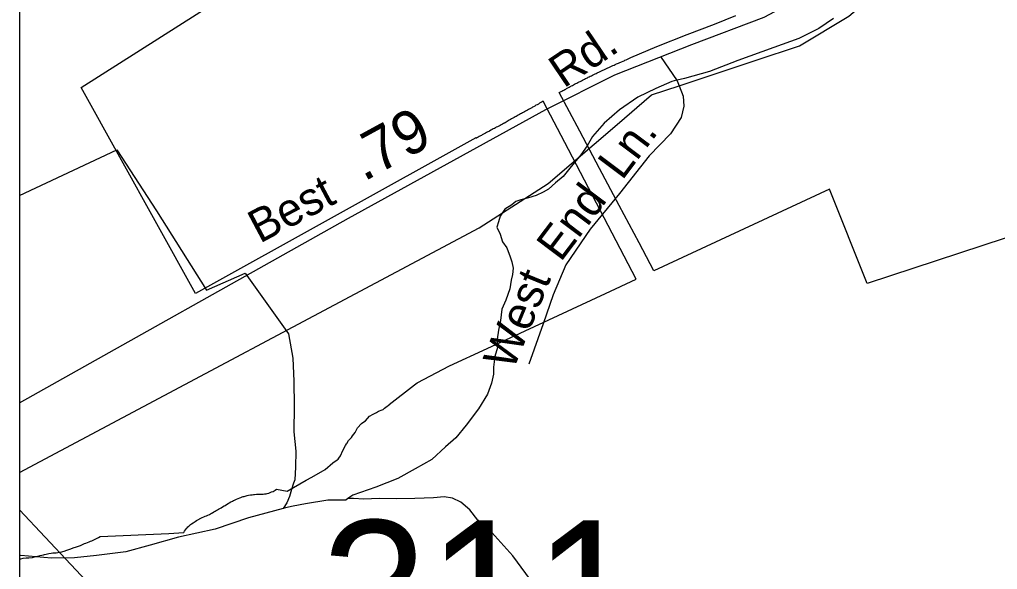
# Model space of a CAD drawing. Extents: x 2315291 to 2336543, y 597177 to 615230.
# Drawn here: x 2315744 to 2318553, y 599617 to 601198 of the extents above; entities that cross this region are included whole.
import ezdxf

# ---------------------------------------------------------------- set-up
doc = ezdxf.new("R2010")
doc.units = 0
for name, color, linetype in [('Exist Boundary Political City Limit New', 7, 'Continuous'), ('Exist Boundary Political Urban Extension UEB', 7, 'Continuous'), ('Exist Hydrographic Misc Water Feature', 7, 'Continuous'), ('Exist Road Non-System Type 51', 7, 'Continuous'), ('Exist Road Non-System Type 51 Label', 7, 'Continuous'), ('Exist Road Secondary Mileage Hundredths English Label', 7, 'Continuous'), ('Exist Road Secondary Structure Standard Bridge Number Label', 7, 'Continuous'), ('Exist Road Secondary Type 51 Attributed', 7, 'Continuous'), ('Exist Road Secondary Type 51 Label', 7, 'Continuous'), ('Exist Utilities Electrical Transmission Line', 7, 'Continuous'), ('Map Preparation Boundary City Limit Buffer Line', 7, 'Continuous')]:
    doc.layers.add(name, color=color, linetype=linetype)

msp = doc.modelspace()

# ---------------------------------------------------------------- linework, layer by layer
at = {"layer": 'Exist Boundary Political City Limit New'}
msp.add_line((2315744.5, 601767.6), (2315744.5, 599647.3), dxfattribs=at)
for points in [[(2315744.5, 604723.7), (2315744.5, 597529.5), (2327185.3, 597529.5)], [(2317108.8, 600884.8), (2317105.2, 600883), (2317101.8, 600881.1), (2317098.2, 600879.2), (2317094.5, 600877.2), (2317092, 600875.9), (2317089.2, 600874.4), (2317085.8, 600872.5), (2317083.2, 600871.1), (2317080.5, 600869.7), (2317077, 600867.8), (2317073.5, 600865.8), (2317071, 600864.4), (2317068.2, 600862.9), (2317064.8, 600861), (2317061.5, 600859.1), (2317057.8, 600857.1), (2317054.8, 600855.4), (2317055.2, 600857.5), (2316249.5, 600409.7), (2315921.8, 601002.4), (2316312.2, 601250.2)], [(2317415.8, 601050.1), (2317419.5, 601051.8), (2317423, 601053.5), (2317426.8, 601055.2), (2317430.2, 601056.8), (2317434, 601058.6), (2317437.5, 601060.2), (2317441.2, 601061.9), (2317444.8, 601063.5), (2317448.5, 601065.2), (2317452.2, 601066.8), (2317455.8, 601068.4), (2317459.5, 601070.1), (2317462.2, 601071.3), (2317465, 601072.6), (2317468.8, 601074.1), (2317471.5, 601075.3), (2317474, 601076.5), (2317478, 601078.1), (2317480.8, 601079.3), (2317483.2, 601080.5), (2317487.2, 601082.1), (2317500, 601088.4), (2317574.8, 601120.2), (2317662.2, 601154.6), (2317740.8, 601184.1), (2317801.8, 601209.1)], [(2319038.8, 600721.7), (2318179, 600438.4), (2318071, 600710), (2317566.8, 600475.2), (2317524, 600555.8), (2317467, 600663.4), (2317410.5, 600769.6), (2317353.8, 600876.4), (2317294.5, 600987.6), (2317298, 600989.5), (2317302, 600991.7), (2317305.5, 600993.6), (2317308.2, 600995), (2317310.8, 600996.5), (2317313.5, 600997.9), (2317316, 600999.3), (2317319.5, 601001.2), (2317323, 601003.2), (2317326.5, 601005), (2317330, 601006.9), (2317332.8, 601008.3), (2317335.2, 601009.7), (2317339, 601011.6), (2317342.5, 601013.5), (2317345.2, 601014.9), (2317347.8, 601016.2), (2317351.5, 601018.1), (2317354.8, 601019.9), (2317358.5, 601021.8), (2317361.2, 601023.1), (2317363.8, 601024.5), (2317367.2, 601026.3), (2317370, 601027.7), (2317372.8, 601029), (2317375.5, 601030.4), (2317378, 601031.7), (2317380.8, 601033.1), (2317383.5, 601034.4), (2317387, 601036.1), (2317390.5, 601037.9), (2317394.2, 601039.7), (2317397.8, 601041.4), (2317400.5, 601042.8), (2317403.2, 601044.1), (2317406, 601045.3), (2317408.5, 601046.6), (2317412.2, 601048.3), (2317415.8, 601050.1)], [(2316430, 599833.1), (2316435, 599832.9), (2316438.2, 599832.9), (2316443.8, 599833.1), (2316448.2, 599833.7), (2316452.5, 599834.4), (2316456.2, 599835.2), (2316460.2, 599836.4), (2316464.8, 599837.9), (2316468.5, 599839.3), (2316472.5, 599841.2), (2316478.8, 599844.9), (2316482.8, 599847.5), (2316512.8, 599841.5), (2316568, 599872.9), (2316584.5, 599882.1), (2316622.8, 599904.1), (2316644, 599922.9), (2316656.8, 599931.5), (2316659.8, 599933.6), (2316661.8, 599936.3), (2316666.8, 599942.9), (2316673.2, 599958.5), (2316680.8, 599972.6), (2316683.2, 599978), (2316684.8, 599978.7), (2316689, 599987.1), (2316695.8, 599994), (2316698, 599996.2), (2316701.2, 600000.5), (2316708.5, 600010.5), (2316711, 600015.8), (2316715, 600023.5), (2316726.8, 600036.5), (2316733.8, 600041.2), (2316738.2, 600044.3), (2316750, 600057.4), (2316760.5, 600062.6), (2316769.5, 600067.8), (2316776, 600071.7), (2316786.5, 600075.6), (2316789, 600076.9), (2316792.8, 600080.5), (2316800, 600085.6), (2316805.8, 600090.1), (2316806, 600090.9), (2316879, 600147.5), (2316886.5, 600153.3), (2316979.8, 600201.8), (2317087.5, 600251.9), (2317427.8, 600410.4), (2317515.8, 600451.4), (2317321.5, 600823.6), (2317248.8, 600962.6), (2317245.2, 600960.7), (2317241.8, 600958.8), (2317238.2, 600956.8), (2317234.8, 600954.8), (2317231.2, 600952.9), (2317227.8, 600951), (2317224.2, 600949), (2317220.8, 600947.1), (2317218.2, 600945.6), (2317215.8, 600944.2), (2317212.2, 600942.2), (2317208.8, 600940.2), (2317206.2, 600938.8), (2317203.5, 600937.3), (2317200, 600935.4), (2317197.5, 600933.9), (2317194.8, 600932.5), (2317191.2, 600930.6), (2317188.8, 600929.1), (2317186, 600927.6), (2317183.5, 600926.1), (2317180.8, 600924.7), (2317177.2, 600922.7), (2317173.8, 600920.8), (2317171.2, 600919.2), (2317168.5, 600917.8), (2317165, 600915.8), (2317161.5, 600913.8), (2317158, 600911.9), (2317154.5, 600909.9), (2317151, 600907.9), (2317147.8, 600906), (2317145.2, 600904.5), (2317142.5, 600903), (2317139, 600901), (2317136.5, 600899.6), (2317135.5, 600899), (2317134.5, 600898.5), (2317131.8, 600897.1), (2317128, 600895.2), (2317124.8, 600893.3), (2317121, 600891.4), (2317117.5, 600889.6), (2317114, 600887.8), (2317111.5, 600886.3), (2317108.8, 600884.8)], [(2315744.5, 599647.3), (2315747.8, 599647.4), (2315755.2, 599648.8), (2315763.5, 599650), (2315771, 599650.3), (2315782, 599651.2), (2315787.8, 599652.6), (2315797, 599655), (2315803.5, 599656.7), (2315812.8, 599658.9), (2315815.8, 599659.6), (2315821, 599660.8), (2315829, 599662.6), (2315835.2, 599663.4), (2315840, 599664), (2315845.2, 599664.5), (2315849.2, 599664.6), (2315854.8, 599665.4), (2315866, 599667.3), (2315868.8, 599667.9), (2315872.2, 599669.2), (2315879.8, 599672.1), (2315891.5, 599676.1), (2315898.8, 599678.8), (2315908.2, 599681.7), (2315914.2, 599683.5), (2315919.8, 599685.8), (2315925, 599688), (2315931.2, 599690.8), (2315935.2, 599692.4), (2315939.8, 599694.2), (2315944, 599696.2), (2315947.8, 599697.6), (2315952.2, 599699.2), (2315962, 599703.5), (2315971.2, 599708.5), (2315976.2, 599711.1), (2316173, 599720.1), (2316216.2, 599722.8), (2316218.5, 599726.8), (2316220.8, 599730.3), (2316223, 599733.2), (2316225.5, 599736.1), (2316228.2, 599739.3), (2316230.5, 599741.3), (2316233.5, 599744), (2316235.8, 599745.9), (2316238.8, 599748.1), (2316242.8, 599750.8), (2316245.8, 599752.7), (2316249, 599754.8), (2316253, 599757.2), (2316256.2, 599759.1), (2316260.2, 599761.5), (2316261.8, 599762.2), (2316264.8, 599763.8), (2316269, 599765.8), (2316274.2, 599768.1), (2316277.8, 599769.6), (2316281, 599770.9), (2316285.5, 599772.4), (2316289.8, 599774.7), (2316292.5, 599776.2), (2316295.5, 599778), (2316298.8, 599779.8), (2316303, 599782.2), (2316306, 599783.9), (2316309.2, 599785.7), (2316313.2, 599788.1), (2316316.2, 599789.9), (2316319.5, 599791.6), (2316323.8, 599794.1), (2316327.8, 599796.4), (2316332.5, 599799.1), (2316335.5, 599800.9), (2316339.2, 599803.1), (2316343.5, 599805.8), (2316346.5, 599807.8), (2316351.5, 599810.6), (2316355.8, 599813), (2316358.8, 599814.6), (2316361.5, 599816), (2316367.5, 599818.8), (2316372, 599820.7), (2316377.2, 599822.7), (2316380.5, 599823.9), (2316384, 599825.1), (2316387, 599825.9), (2316389.8, 599826.8), (2316392.8, 599827.6), (2316395.5, 599828.3), (2316398.5, 599829), (2316402, 599829.8), (2316408, 599830.9), (2316412.5, 599831.6), (2316416.2, 599832), (2316419.8, 599832.4), (2316425.5, 599832.8), (2316430, 599833.1)]]:
    msp.add_lwpolyline(points, dxfattribs=at)
at = {"layer": 'Exist Boundary Political Urban Extension UEB'}
for points in [[(2317638.9, 601007.3), (2317857.2, 601080), (2317984.6, 601122.5), (2318126.2, 601207.5), (2318310.3, 601363.2), (2318542.1, 601594.9)], [(2315744.5, 599894.9), (2317064.3, 600598.7), (2317262.5, 600726.1), (2317460.7, 600896), (2317559.8, 600980.9), (2317638.9, 601007.3)]]:
    msp.add_lwpolyline(points, dxfattribs=at)
at = {"layer": 'Exist Hydrographic Misc Water Feature'}
for points in [[(2318082.4, 601200.5), (2318040.6, 601171.9), (2317982.8, 601143.3), (2317911.2, 601116.8), (2317807.7, 601079.6), (2317726, 601048.5), (2317654.7, 601028.1), (2317624.8, 601021.6), (2317618.4, 601019.7), (2317572.5, 600999), (2317520.8, 600974.4), (2317467.5, 600937.8), (2317424.2, 600899.3), (2317390.2, 600861), (2317374.8, 600835), (2317356.7, 600808.9), (2317325.4, 600770.6), (2317305.7, 600746.4), (2317284, 600728.2), (2317264.3, 600710.1), (2317248.1, 600701.6), (2317228, 600691.6), (2317206.2, 600685.2), (2317184.3, 600679.1), (2317170.4, 600674.7), (2317158.7, 600664.8), (2317138.8, 600652.7), (2317125.2, 600632.5), (2317120.7, 600616.5), (2317115.2, 600600.3), (2317125.5, 600580.5), (2317132, 600558.4), (2317143.9, 600540.9), (2317154, 600515), (2317158.1, 600501), (2317162.8, 600482.9), (2317160.5, 600464.9), (2317157, 600448.8), (2317153.1, 600423.1), (2317141.4, 600390.8), (2317129.8, 600364.5), (2317126.3, 600332.6), (2317120.7, 600304.6), (2317116.8, 600278.5), (2317117, 600254.5), (2317109.3, 600228.5), (2317105.6, 600198.6), (2317105.8, 600178.4), (2317100, 600152.4), (2317088.3, 600120.6), (2317063.1, 600078.1), (2317027.2, 600031.6), (2316997.9, 599995.5), (2316968, 599969.2), (2316928.4, 599932.5), (2316880.6, 599906.1), (2316831.2, 599877.8), (2316767.6, 599852.9), (2316701.8, 599830.4), (2316687.9, 599820.3)], [(2315744.5, 600691.3), (2316023.7, 600822.6), (2316137.5, 600647.7), (2316281.9, 600419.6), (2316392.8, 600468.6), (2316464.4, 600367.4), (2316517.3, 600294.1), (2316529.8, 600224.5), (2316532.4, 600158.4), (2316533.3, 600086.5), (2316532, 600012.5), (2316538.4, 599956.4), (2316537, 599910.3), (2316535.3, 599874.5), (2316531.6, 599864.5), (2316525.5, 599846.3), (2316520.1, 599826.5), (2316511.9, 599808.3), (2316502.1, 599792.3)], [(2316687.9, 599820.3), (2316681.9, 599815.9), (2316630, 599815.6), (2316566.3, 599805), (2316530.4, 599798.6), (2316508.4, 599794.2), (2316502.1, 599792.3)], [(2317222.4, 599572), (2317161.5, 599655.3), (2317100.8, 599722.5), (2317060.4, 599758.2), (2317037.7, 599787.9), (2317011.6, 599809.7), (2316987.7, 599821.4), (2316963.7, 599825), (2316933.9, 599823), (2316880, 599820.2), (2316825.9, 599819.8), (2316777.7, 599821), (2316733.8, 599818.7), (2316703.5, 599820.4), (2316687.9, 599820.3)], [(2316502.1, 599792.3), (2316402.4, 599765.1), (2316306.7, 599732.1), (2316201.3, 599709), (2316119.3, 599686.1), (2316050, 599667.3), (2315965.7, 599656.5), (2315902.5, 599649.8), (2315836.1, 599649.2), (2315748.1, 599656.4), (2315744.5, 599655.9)]]:
    msp.add_lwpolyline(points, dxfattribs=at)
at = {"layer": 'Exist Road Non-System Type 51'}
for points in [[(2317585.9, 601091.7), (2317633.5, 601021.2), (2317638.9, 601007.3)], [(2317638.9, 601007.3), (2317650.6, 600977.4), (2317652.6, 600948.8), (2317644.9, 600916.4), (2317614.5, 600868.7), (2317553.5, 600805.8), (2317467.8, 600697.2), (2317384, 600595.2), (2317313.5, 600492.3), (2317277.3, 600406.6), (2317248.8, 600322.7), (2317206.9, 600206.4)]]:
    msp.add_lwpolyline(points, dxfattribs=at)
at = {"layer": 'Exist Road Secondary Type 51 Attributed'}
msp.add_lwpolyline([(2315744.5, 600095.6), (2316689.5, 600626.2), (2317256.4, 600939.2), (2317454.5, 601038.4), (2317675.4, 601126), (2317883, 601204.2), (2317991.6, 601263.2), (2318258.2, 601461.5), (2318357.3, 601541.5), (2318498.2, 601663.5)], dxfattribs=at)
at = {"layer": 'Exist Utilities Electrical Transmission Line'}
msp.add_line((2315744.5, 599788.2), (2316288, 599208.6), dxfattribs=at)
at = {"layer": 'Map Preparation Boundary City Limit Buffer Line'}
msp.add_line((2315744.5, 601767.6), (2315744.5, 599647.3), dxfattribs=at)
for points in [[(2315744.5, 604723.7), (2315744.5, 597529.5), (2327185.3, 597529.5)], [(2317108.8, 600884.8), (2317105.2, 600883), (2317101.8, 600881.1), (2317098.2, 600879.2), (2317094.5, 600877.2), (2317092, 600875.9), (2317089.2, 600874.4), (2317085.8, 600872.5), (2317083.2, 600871.1), (2317080.5, 600869.7), (2317077, 600867.8), (2317073.5, 600865.8), (2317071, 600864.4), (2317068.2, 600862.9), (2317064.8, 600861), (2317061.5, 600859.1), (2317057.8, 600857.1), (2317054.8, 600855.4), (2317055.2, 600857.5), (2316249.5, 600409.7), (2315921.8, 601002.4), (2316312.2, 601250.2)], [(2317415.8, 601050.1), (2317419.5, 601051.8), (2317423, 601053.5), (2317426.8, 601055.2), (2317430.2, 601056.8), (2317434, 601058.6), (2317437.5, 601060.2), (2317441.2, 601061.9), (2317444.8, 601063.5), (2317448.5, 601065.2), (2317452.2, 601066.8), (2317455.8, 601068.4), (2317459.5, 601070.1), (2317462.2, 601071.3), (2317465, 601072.6), (2317468.8, 601074.1), (2317471.5, 601075.3), (2317474, 601076.5), (2317478, 601078.1), (2317480.8, 601079.3), (2317483.2, 601080.5), (2317487.2, 601082.1), (2317500, 601088.4), (2317574.8, 601120.2), (2317662.2, 601154.6), (2317740.8, 601184.1), (2317801.8, 601209.1)], [(2319038.8, 600721.7), (2318179, 600438.4), (2318071, 600710), (2317566.8, 600475.2), (2317524, 600555.8), (2317467, 600663.4), (2317410.5, 600769.6), (2317353.8, 600876.4), (2317294.5, 600987.6), (2317298, 600989.5), (2317302, 600991.7), (2317305.5, 600993.6), (2317308.2, 600995), (2317310.8, 600996.5), (2317313.5, 600997.9), (2317316, 600999.3), (2317319.5, 601001.2), (2317323, 601003.2), (2317326.5, 601005), (2317330, 601006.9), (2317332.8, 601008.3), (2317335.2, 601009.7), (2317339, 601011.6), (2317342.5, 601013.5), (2317345.2, 601014.9), (2317347.8, 601016.2), (2317351.5, 601018.1), (2317354.8, 601019.9), (2317358.5, 601021.8), (2317361.2, 601023.1), (2317363.8, 601024.5), (2317367.2, 601026.3), (2317370, 601027.7), (2317372.8, 601029), (2317375.5, 601030.4), (2317378, 601031.7), (2317380.8, 601033.1), (2317383.5, 601034.4), (2317387, 601036.1), (2317390.5, 601037.9), (2317394.2, 601039.7), (2317397.8, 601041.4), (2317400.5, 601042.8), (2317403.2, 601044.1), (2317406, 601045.3), (2317408.5, 601046.6), (2317412.2, 601048.3), (2317415.8, 601050.1)], [(2316430, 599833.1), (2316435, 599832.9), (2316438.2, 599832.9), (2316443.8, 599833.1), (2316448.2, 599833.7), (2316452.5, 599834.4), (2316456.2, 599835.2), (2316460.2, 599836.4), (2316464.8, 599837.9), (2316468.5, 599839.3), (2316472.5, 599841.2), (2316478.8, 599844.9), (2316482.8, 599847.5), (2316512.8, 599841.5), (2316568, 599872.9), (2316584.5, 599882.1), (2316622.8, 599904.1), (2316644, 599922.9), (2316656.8, 599931.5), (2316659.8, 599933.6), (2316661.8, 599936.3), (2316666.8, 599942.9), (2316673.2, 599958.5), (2316680.8, 599972.6), (2316683.2, 599978), (2316684.8, 599978.7), (2316689, 599987.1), (2316695.8, 599994), (2316698, 599996.2), (2316701.2, 600000.5), (2316708.5, 600010.5), (2316711, 600015.8), (2316715, 600023.5), (2316726.8, 600036.5), (2316733.8, 600041.2), (2316738.2, 600044.3), (2316750, 600057.4), (2316760.5, 600062.6), (2316769.5, 600067.8), (2316776, 600071.7), (2316786.5, 600075.6), (2316789, 600076.9), (2316792.8, 600080.5), (2316800, 600085.6), (2316805.8, 600090.1), (2316806, 600090.9), (2316879, 600147.5), (2316886.5, 600153.3), (2316979.8, 600201.8), (2317087.5, 600251.9), (2317427.8, 600410.4), (2317515.8, 600451.4), (2317321.5, 600823.6), (2317248.8, 600962.6), (2317245.2, 600960.7), (2317241.8, 600958.8), (2317238.2, 600956.8), (2317234.8, 600954.8), (2317231.2, 600952.9), (2317227.8, 600951), (2317224.2, 600949), (2317220.8, 600947.1), (2317218.2, 600945.6), (2317215.8, 600944.2), (2317212.2, 600942.2), (2317208.8, 600940.2), (2317206.2, 600938.8), (2317203.5, 600937.3), (2317200, 600935.4), (2317197.5, 600933.9), (2317194.8, 600932.5), (2317191.2, 600930.6), (2317188.8, 600929.1), (2317186, 600927.6), (2317183.5, 600926.1), (2317180.8, 600924.7), (2317177.2, 600922.7), (2317173.8, 600920.8), (2317171.2, 600919.2), (2317168.5, 600917.8), (2317165, 600915.8), (2317161.5, 600913.8), (2317158, 600911.9), (2317154.5, 600909.9), (2317151, 600907.9), (2317147.8, 600906), (2317145.2, 600904.5), (2317142.5, 600903), (2317139, 600901), (2317136.5, 600899.6), (2317135.5, 600899), (2317134.5, 600898.5), (2317131.8, 600897.1), (2317128, 600895.2), (2317124.8, 600893.3), (2317121, 600891.4), (2317117.5, 600889.6), (2317114, 600887.8), (2317111.5, 600886.3), (2317108.8, 600884.8)], [(2315744.5, 599647.3), (2315747.8, 599647.4), (2315755.2, 599648.8), (2315763.5, 599650), (2315771, 599650.3), (2315782, 599651.2), (2315787.8, 599652.6), (2315797, 599655), (2315803.5, 599656.7), (2315812.8, 599658.9), (2315815.8, 599659.6), (2315821, 599660.8), (2315829, 599662.6), (2315835.2, 599663.4), (2315840, 599664), (2315845.2, 599664.5), (2315849.2, 599664.6), (2315854.8, 599665.4), (2315866, 599667.3), (2315868.8, 599667.9), (2315872.2, 599669.2), (2315879.8, 599672.1), (2315891.5, 599676.1), (2315898.8, 599678.8), (2315908.2, 599681.7), (2315914.2, 599683.5), (2315919.8, 599685.8), (2315925, 599688), (2315931.2, 599690.8), (2315935.2, 599692.4), (2315939.8, 599694.2), (2315944, 599696.2), (2315947.8, 599697.6), (2315952.2, 599699.2), (2315962, 599703.5), (2315971.2, 599708.5), (2315976.2, 599711.1), (2316173, 599720.1), (2316216.2, 599722.8), (2316218.5, 599726.8), (2316220.8, 599730.3), (2316223, 599733.2), (2316225.5, 599736.1), (2316228.2, 599739.3), (2316230.5, 599741.3), (2316233.5, 599744), (2316235.8, 599745.9), (2316238.8, 599748.1), (2316242.8, 599750.8), (2316245.8, 599752.7), (2316249, 599754.8), (2316253, 599757.2), (2316256.2, 599759.1), (2316260.2, 599761.5), (2316261.8, 599762.2), (2316264.8, 599763.8), (2316269, 599765.8), (2316274.2, 599768.1), (2316277.8, 599769.6), (2316281, 599770.9), (2316285.5, 599772.4), (2316289.8, 599774.7), (2316292.5, 599776.2), (2316295.5, 599778), (2316298.8, 599779.8), (2316303, 599782.2), (2316306, 599783.9), (2316309.2, 599785.7), (2316313.2, 599788.1), (2316316.2, 599789.9), (2316319.5, 599791.6), (2316323.8, 599794.1), (2316327.8, 599796.4), (2316332.5, 599799.1), (2316335.5, 599800.9), (2316339.2, 599803.1), (2316343.5, 599805.8), (2316346.5, 599807.8), (2316351.5, 599810.6), (2316355.8, 599813), (2316358.8, 599814.6), (2316361.5, 599816), (2316367.5, 599818.8), (2316372, 599820.7), (2316377.2, 599822.7), (2316380.5, 599823.9), (2316384, 599825.1), (2316387, 599825.9), (2316389.8, 599826.8), (2316392.8, 599827.6), (2316395.5, 599828.3), (2316398.5, 599829), (2316402, 599829.8), (2316408, 599830.9), (2316412.5, 599831.6), (2316416.2, 599832), (2316419.8, 599832.4), (2316425.5, 599832.8), (2316430, 599833.1)]]:
    msp.add_lwpolyline(points, dxfattribs=at)

# ---------------------------------------------------------------- texts
at = {"layer": 'Exist Road Non-System Type 51 Label'}
for s, rotation, p in [('Ln.', 53.1242, (2317475.3, 600733)), ('End', 53.0867, (2317298.9, 600498.1)), ('West', 67.6617, (2317161.7, 600185.8))]:
    msp.add_text(s, height=95, rotation=rotation, dxfattribs=at).set_placement(p)
at = {"layer": 'Exist Road Secondary Mileage Hundredths English Label'}
msp.add_text('.79', height=125, rotation=28.592, dxfattribs=at).set_placement((2316733.1, 600730.4))
at = {"layer": 'Exist Road Secondary Structure Standard Bridge Number Label'}
msp.add_text('311', height=410.1, dxfattribs=at).set_placement((2316611.7, 599347.4))
at = {"layer": 'Exist Road Secondary Type 51 Label'}
for s, rotation, p in [('Rd.', 34.0543, (2317307.5, 600998.6)), ('Best', 27.9448, (2316434.3, 600552.7))]:
    msp.add_text(s, height=95, rotation=rotation, dxfattribs=at).set_placement(p)

doc.saveas('drawing.dxf')
